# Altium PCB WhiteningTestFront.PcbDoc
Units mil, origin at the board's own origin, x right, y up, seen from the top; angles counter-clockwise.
Board outline 11100 x 1500 mil, 2 copper layers (Top Layer, Bottom Layer), stack 60.8 mil thick; 15 components, 48 nets, 141 pads, 16 vias.
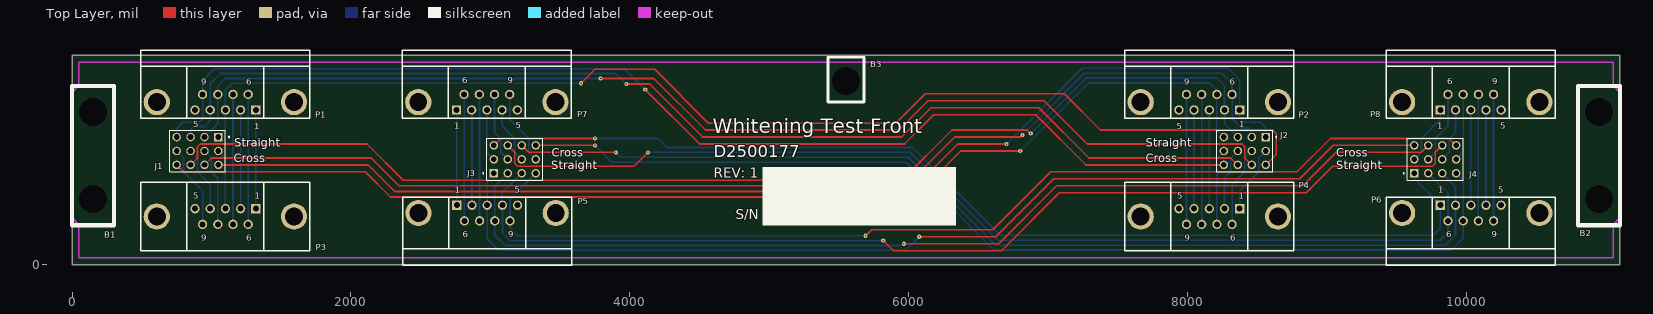
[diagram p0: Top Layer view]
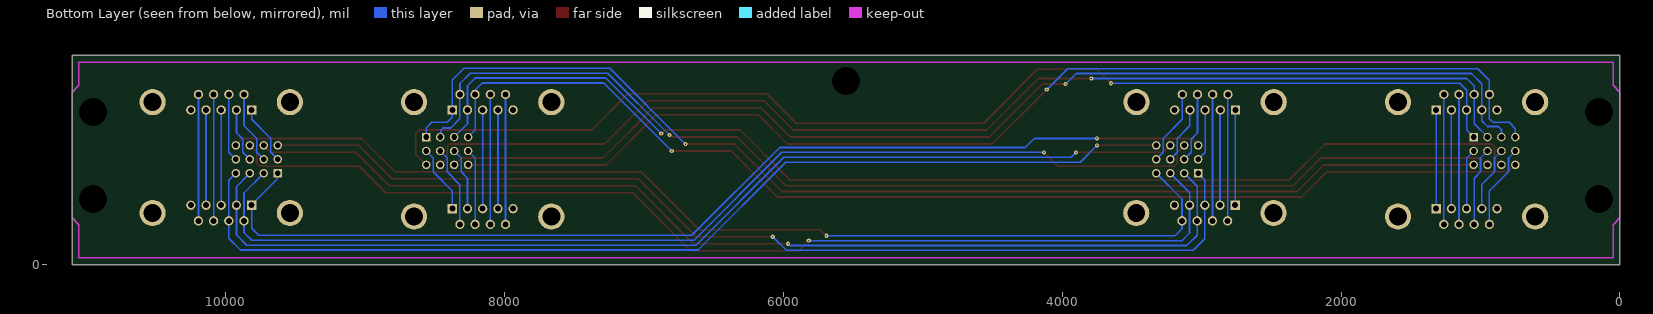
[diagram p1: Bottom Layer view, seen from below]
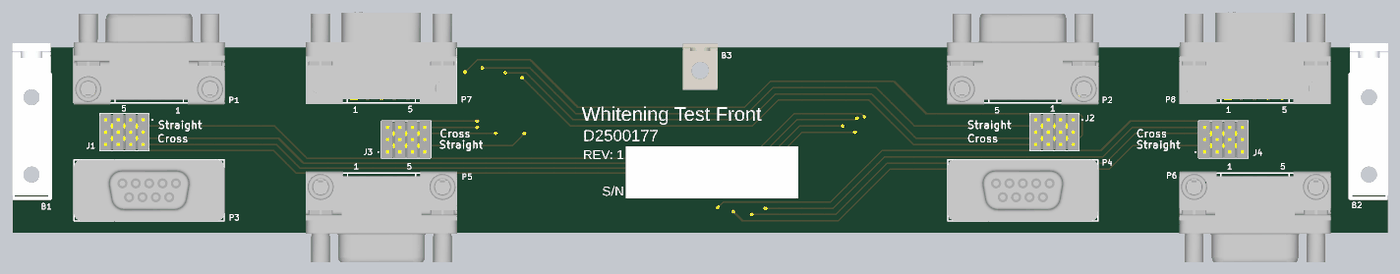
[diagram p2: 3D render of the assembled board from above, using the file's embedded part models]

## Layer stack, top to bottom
Top Solder: solder mask 0.4, Solder Resist, Dk 3.5
Top Layer: signal copper 1.4
Dielectric 1: dielectric 58, FR-4, Dk 4.8
Bottom Layer: signal copper 1.4
Bottom Solder: solder mask 0.4, Solder Resist, Dk 3.5

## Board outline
0,0 11100,0 11100,1500 0,1500

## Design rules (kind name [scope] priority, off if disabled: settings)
Clearance Clearance_relaydriver [HasFootprint('SOTFL50P160X60-6N')] p1: gap=10 ignorepadtopadclearanceinfootprint=TRUE except(8: Arc-Arc Arc-Track Arc-SMDPad Track-Track Track-SMDPad SMDPad-SMDPad)
Clearance Clearance_8mils [InNetClass('Clearance8mils') vs InNetClass('Clearance8mils')] p2: gap=10 ignorepadtopadclearanceinfootprint=TRUE except(8: Arc-Arc Arc-Track Track-Track)
Clearance [All] p3: gap=10 ignorepadtopadclearanceinfootprint=FALSE
ComponentClearance ComponentClearance_Collision [InComponentClass('ComponentCollision') vs InComponentClass('ComponentCollision')] p1: gap=-2000 collisioncheckmode=3 verticalgap=10 showdistances=FALSE
ComponentClearance [All] p2: gap=10 collisioncheckmode=3 verticalgap=10 showdistances=FALSE
HoleSize [All] p1: absolutevalues=TRUE maxlimit=200 minlimit=8 maxpercent=80.000 minpercent=20.000
MinimumAnnularRing [All] p1: minimumring=10
MinimumSolderMaskSliver [All] p1: minsoldermaskwidth=0
PolygonConnect [All] p1: connectstyle=Relief reliefconductorwidth=10 reliefentries=4 polygonreliefangle="90 Angle" airgapwidth=10
RoutingVias [All] p1: holewidth=15 width=35 viastyle="Through Hole" minholewidth=10 minwidth=25 maxholewidth=28 maxwidth=50
SilkToSolderMaskClearance [IsPad] p1: minsilkscreentomaskgap=2 clearancetoexposedcopper=TRUE
SolderMaskExpansion [All] p1: expansion=4 istentingtop=FALSE
Width [All] p1: maxlimit=100 minlimit=8 preferedwidth=10
26 further rules are at their usual default settings.

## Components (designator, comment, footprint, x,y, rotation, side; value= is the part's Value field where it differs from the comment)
B1 "Bracket" Bracket-RA_708#1 150,1095 r180 top
B2 "Bracket" Bracket-RA_708#2 10950,1095 r180 top
B3 "Bracket" Bracket-RA_634 5550,1317 r180 top
J1 "TSW-104-07-L-T" SAMTEC_TSW-104-07-L-T 900,815 r180 top
J2 "TSW-104-07-L-T" SAMTEC_TSW-104-07-L-T 8410,815 r180 top
J3 "TSW-104-07-L-T" SAMTEC_TSW-104-07-L-T 3175,755 r0 top
J4 "TSW-104-07-L-T" SAMTEC_TSW-104-07-L-T 9775,755 r0 top
P1 "DB9M" DB9M-RA 1100,1165 r0 top locked
P2 "DB9M" DB9M-RA 8155,1165 r0 top locked
P3 "DB9F" DB9F-ST 1100,345 r0 top locked
P4 "DB9F" DB9F-ST 8155,345 r0 top locked
P5 "DB9M" DB9M-RA 2977,370 r180 top locked
P6 "DB9M" DB9M-RA 10030,370 r180 top locked
P7 "DB9F" DB9F-RA 2975,1165 r0 top locked
P8 "DB9F" DB9F-RA 10030,1165 r0 top locked

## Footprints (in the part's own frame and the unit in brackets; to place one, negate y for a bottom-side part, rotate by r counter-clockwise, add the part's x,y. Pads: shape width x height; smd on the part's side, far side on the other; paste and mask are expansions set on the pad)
Bracket-RA_634 [mil] "Keystone Electronics right-angle 6-32 steel, 634"
  round 0 hole 200 unplated: 1(0,0)
  silkscreen extent -130,-170 130,150, body extent -141,-215 141,160, height 375
Bracket-RA_708#1 [mil] "Keystone Electronics right-angle 6-32 steel, 708"
  round 0 hole 200 unplated: 1(0,0) 2(0,625)
  silkscreen extent -150,-187 150,813, body extent -156,-439 156,791, height 390
Bracket-RA_708#2 [mil] "Keystone Electronics right-angle 6-32 steel, 708"
  round 0 hole 200 unplated: 1(0,0)
  oval 250x0 hole 200 unplated: 2(0,625)
  silkscreen extent -150,-187 150,813, body extent -156,-439 156,791, height 390
DB9F-RA [mm] "Receptiacle; D Subminiature 9 Position; Right Angle"
  rect 1.69x1.69 hole 1.09: 1(-5.54,-1.42)
  round 1.69 hole 1.09: 2(-2.77,-1.42) 3(0,-1.42) 4(2.77,-1.42) 5(5.54,-1.42) 6(-4.155,1.42) 7(-1.385,1.42) 8(1.385,1.42) 9(4.155,1.42)
  round 4.76 hole 3.26: 10(-12.495,0) 11(12.495,0)
  silkscreen extent -15.4,-2.9 15.4,9.5, body extent -15.49,-3.17 15.49,15.72, height 12.62
DB9F-ST [mm] "Receptiacle; D Subminiature 9 Position; Straight"
  rect 1.69x1.69 hole 1.09: 1(5.54,1.42)
  round 1.69 hole 1.09: 2(2.77,1.42) 3(0,1.42) 4(-2.77,1.42) 5(-5.54,1.42) 6(4.155,-1.42) 7(1.385,-1.42) 8(-1.385,-1.42) 9(-4.155,-1.42)
  round 4.76 hole 3.26: 10(12.495,0) 11(-12.495,0)
  silkscreen extent -15.4,-6.27 15.4,6.27, body extent -15.44,-6.3 15.44,6.3, height 12.32
DB9M-RA [mm] "Plug; D Subminiature 9 Position; Right Angle"
  rect 1.69x1.69 hole 1.09: 1(5.54,-1.42)
  round 1.69 hole 1.09: 2(2.77,-1.42) 3(0,-1.42) 4(-2.77,-1.42) 5(-5.54,-1.42) 6(4.155,1.42) 7(1.385,1.42) 8(-1.385,1.42) 9(-4.155,1.42)
  round 4.76 hole 3.26: 10(12.495,0) 11(-12.495,0)
  silkscreen extent -15.4,-2.9 15.4,9.5, body extent -15.52,-3.24 15.52,15.37, height 12.62
SAMTEC_TSW-104-07-L-T [mil]
  rect 61x61 hole 40.16: 01(-150,-100)
  round 61 hole 40.16: 02(-150,0) 03(-150,100) 04(-50,-100) 05(-50,0) 06(-50,100) 07(50,-100) 08(50,0) 09(50,100) 10(150,-100) 11(150,0) 12(150,100)
  silkscreen extent -230,-150 200,150, body extent -200,-150 200,150, height 330

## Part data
B1 B2: library part Bracket_708, "Keystone Electronics right-angle 6-32 steel, 708", Part Number=36-708-ND
B3: library part Bracket_634, "Keystone Electronics right-angle 6-32 steel, 634", Part Number=36-708-ND
J1 J2 J3 J4: Package=None
P1 P2 P5 P6: "Plug Assembly, 9 Position, Right Angle, .318 Series", Part Number=609-4954-ND
P3 P4: "Receptacle Assembly, 9 Position, Right Angle, .318 Series", Part Number=609-5874-ND
P7 P8: "Receptacle Assembly, 9 Position, Right Angle, .318 Series", Part Number=609-6160-ND

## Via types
v1: diameter 30, hole 10, Top Layer to Bottom Layer, 16 vias

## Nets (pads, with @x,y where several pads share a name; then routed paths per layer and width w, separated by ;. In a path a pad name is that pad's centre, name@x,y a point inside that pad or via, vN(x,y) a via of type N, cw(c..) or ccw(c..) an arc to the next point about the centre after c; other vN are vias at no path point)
IN0: P1.6 P3.6 | length 931.8
  Bottom Layer w12: P3.6 P1.6
IN1: P1.7 P3.7 | length 931.8
  Bottom Layer w12: P3.7 P1.7
IN2: J1.05 P3.8 | length 565.5
  Bottom Layer w12: J1.05 1000,765 1000,665 1045.47,619.53 P3.8
IN3: J1.11 P3.9 | length 603.1
  Bottom Layer w12: J1.11 800,765 800,665 936.42,528.58 P3.9
IN4: J2.05 P4.6 | length 584.5
  Bottom Layer w12: P4.6 8318.58,573.58 8410,665 8410,765 J2.05
IN5: J2.11 P4.7 | length 546.8
  Bottom Layer w12: P4.7 8209.53,764.53 J2.11
IN6: P2.8 P4.8 | length 931.8
  Bottom Layer w12: P4.8 P2.8
IN7: P2.9 P4.9 | length 931.8
  Bottom Layer w12: P4.9 P2.9
INN2: J1.04 J2.06 P1.8 | length 8319.8
  Top Layer w12: v1(3790,1335) 4172.35,1335 4542.35,965 5928.58,965 6138.58,1175 6970,1175 7280,865 8390,865 8410,845 8410,765 J2.06
  Bottom Layer w12: J1.04 1045.47,1010.47 P1.8 1045.47,1280.47 1100,1335 v1(3790,1335)
INN3: J1.10 J2.12 P1.9 | length 8369
  Top Layer w12: v1(4110.93,1255) 4500.93,865 ; 4500.93,865 5970,865 6180,1075 6911.45,1075 7271.45,715 J2.12
  Bottom Layer w12: J1.10 750,975 795,1020 910,1020 936.42,1046.42 P1.9 936.42,1321.42 1020,1405 3960.93,1405 v1(4110.93,1255)
INN4: J1.06 J2.04 P2.6 | length 8311.6
  Top Layer w12: J1.06 1000,765 2145,765 2345,565 5980.71,565 6330.71,915 6801,915 v1(6815.5,929.5)
  Bottom Layer w12: v1(6815.5,929.5) 7258.81,1372.81 8244.2,1372.81 8318.25,1298.75 P2.6@8318.25,1220.91 ; P2.6 8318.58,1046.42 8385,980 8440,980 8456.5,963.5 8456.5,918.5 J2.04
INN5: J1.12 J2.10 P2.7 | length 8272.6
  Top Layer w12: J1.12 800,665 2103.58,665 2283.58,485 6042.13,485 6372.13,815 v1(6800,815)
  Bottom Layer w12: v1(6800,815) 7287.81,1302.81 8159.2,1302.81 8209.2,1252.81 P2.7@8209.2,1220.91 ; P2.7 8209.53,965.47 J2.10
INP0: P1.1 P3.1 | length 708.2
  Bottom Layer w12: P3.1 P1.1
INP1: P1.2 P3.2 | length 708.2
  Bottom Layer w12: P3.2 P1.2
INP2: J1.01 J2.03 P1.3 | length 8573.4
  Top Layer w12: v1(3650,1300) 3750,1400 4178.06,1400 4563.06,1015 5907.87,1015 6117.87,1225 7115,1225 7375,965 8610,965 8635,940 8635,790 J2.03
  Bottom Layer w12: J1.01 1100,965 P1.3 1100,1250 1150,1300 v1(3650,1300)
INP3: J1.07 J2.09 P1.4 | length 8330.1
  Top Layer w12: v1(3975,1295) 4141.64,1295 4521.64,915 5949.29,915 6159.29,1125 6932.16,1125 7292.16,765 8310,765 J2.09
  Bottom Layer w12: J1.07 850,968.15 871.85,990 950,990 990.94,1030.94 P1.4 990.94,1295.94 1065,1370 3900,1370 v1(3975,1295)
INP4: J1.03 J2.01 P2.1 | length 8353.2
  Top Layer w12: J1.03 2124.29,715 2314.29,525 6011.42,525 6351.42,865 v1@6700.75,865
  Bottom Layer w12: v1(6700.75,864.25) 7244.31,1407.81 8289.2,1407.81 8372.78,1324.22 P2.1@8372.78,1109.09 ; P2.1 8373.11,1056.89 8410,1020 8520,1020 8560,980 J2.01
INP5: J1.09 J2.07 P2.2 | length 8385.5
  Top Layer w12: J1.09 900,765 900,845 920,865 2115,865 2375,605 5950,605 6310,965 6850,965 v1(6875.25,939.75)
  Bottom Layer w12: v1(6875.25,939.75) 7273.31,1337.81 8209.2,1337.81 8263.72,1283.28 P2.2@8263.72,1109.09 ; P2.2 8264.06,1010.94 J2.07
INP6: P2.3 P4.3 | length 708.2
  Bottom Layer w12: P4.3 P2.3
INP7: P2.4 P4.4 | length 708.2
  Bottom Layer w12: P4.4 P2.4
IP2: J1.02 P3.3 | length 434.8
  Bottom Layer w12: J1.02 1100,765 P3.3
IP3: J1.08 P3.4 | length 472.5
  Bottom Layer w12: J1.08 900,765 900,665 990.95,574.05 P3.4
IP4: J2.02 P4.1 | length 491.5
  Bottom Layer w12: P4.1 8373.11,528.11 8510,665 8510,765 J2.02
IP5: J2.08 P4.2 | length 453.8
  Bottom Layer w12: P4.2 8264.06,619.06 8310,665 8310,765 J2.08
ON0: P5.6 P7.6 | length 901.8
  Bottom Layer w12: P5.6@2813.42,319.09 P7.6@2813.42,1220.91
ON1: P5.7 P7.7 | length 901.8
  Bottom Layer w12: P5.7@2922.47,319.09 P7.7@2922.47,1220.91
ON2: J3.04 J4.06 P5.8 | length 7503.6
  Top Layer w12: v1(5965,150) 6644.29,150 7059.29,565 8825,565 9065,805 9675,805 J4.06
  Bottom Layer w12: P5.8@3031.53,289.09 3031.53,561.53 J3.04 ; P5.8@3031.86,289.09 3031.86,211.25 3105.91,137.19 5952.19,137.19 v1(5965,150)
ON3: J3.10 J4.12 P5.9 | length 7588.7
  Top Layer w12: v1(5690.91,207.19) 5733.72,250 6602.87,250 7017.87,665 8783.58,665 9023.58,905 9875,905 J4.12
  Bottom Layer w12: P5.9@3140.58,289.09 3140.58,470.58 J3.10 ; P5.9@3140.91,289.09 3140.91,257.19 3190.91,207.19 v1(5690.91,207.19)
ON4: J3.06 J4.04 P6.6 | length 7659.4
  Top Layer w12: J3.06 3175,805 3175,725 3195,705 4030,705 v1(4130,805)
  Bottom Layer w12: v1(4130,805) 6010.5,805 6640.5,175 9811.89,175 9866.42,229.53 9866.42,289.09 9866.42,513.58 J4.04
ON5: J3.12 J4.10 P6.7 | length 7483.1
  Top Layer w12: J3.12 v1(3750,855)
  Bottom Layer w12: v1(3750,855) 3870,735 5981.51,735 6611.51,105 9891.89,105 9975.47,188.58 9975.47,289.09 9975.47,604.53 J4.10
ON6: P6.8 P8.8 | length 901.8
  Bottom Layer w12: P6.8@10084.53,319.09 P8.8
ON7: P6.9 P8.9 | length 901.8
  Bottom Layer w12: P6.9@10193.58,319.09 P8.9
OP0: P5.1 P7.1 | length 678.2
  Bottom Layer w12: P5.1@2758.89,430.9 P7.1@2758.89,1109.09
OP1: P5.2 P7.2 | length 678.2
  Bottom Layer w12: P5.2@2867.94,430.9 P7.2@2867.94,1109.09
OP2: J3.01 J4.03 P5.3 | length 7483.2
  Top Layer w12: v1(6075,200) 6623.58,200 7038.58,615 8804.29,615 9044.29,855 J4.03
  Bottom Layer w12: P5.3@2977,400.9 2977,607 J3.01 ; P5.3@2977.33,400.9 2977.33,185.78 3060.91,102.19 5977.19,102.19 v1(6075,200)
OP3: J3.07 J4.09 P5.4 | length 7636.7
  Top Layer w12: v1(5817.5,172.5) 5890,100 6665,100 7080,515 8850,515 9040,705 9755,705 9775,725 9775,805 J4.09
  Bottom Layer w12: P5.4@3086.06,400.9 3086.06,516.06 J3.07 ; P5.4@3086.39,400.9 3086.39,226.72 3140.91,172.19 v1@5817.5,172.19
OP4: J3.03 J4.01 P6.1 | length 7558.6
  Top Layer w12: J3.03 3075,905 v1(3750,905)
  Bottom Layer w12: v1(3750,905) 4200,905 4265,840 6025,840 6655,210 9761.89,210 9811.89,260 P6.1@9811.89,400.9 ; J4.01 9629.27,650.73 9629.27,613.53 P6.1@9811.89,430.9
OP5: J3.09 J4.07 P6.2 | length 7503.5
  Top Layer w12: J3.09 3275,805 v1(3900,805)
  Bottom Layer w12: v1(3900,805) 3935,770 5996,770 6626.01,140 9846.89,140 9920.94,214.06 9920.94,400.9 9920.94,559.06 J4.07
OP6: P6.3 P8.3 | length 678.2
  Bottom Layer w12: P6.3@10030,430.9 P8.3
OP7: P6.4 P8.4 | length 678.2
  Bottom Layer w12: P6.4@10139.06,430.9 P8.4
OUTN2: J3.05 P7.8 | length 505.5
  Bottom Layer w12: P7.8 3029.53,945.47 3075,900 3075,805 J3.05
OUTN3: J3.11 P7.9 | length 543.1
  Bottom Layer w12: P7.9 3138.58,1041.42 3275,905 3275,805 J3.11
OUTN4: J4.05 P8.6 | length 524.5
  Bottom Layer w12: J4.05 9775,805 9775,905 9866.42,996.42 P8.6
OUTN5: J4.11 P8.7 | length 486.8
  Bottom Layer w12: J4.11 9975.47,805.47 P8.7
OUTP2: J3.02 P7.3 | length 374.8
  Bottom Layer w12: P7.3 2975,805 J3.02
OUTP3: J3.08 P7.4 | length 412.5
  Bottom Layer w12: P7.4 3084.06,995.94 3175,905 3175,805 J3.08
OUTP4: J4.02 P8.1 | length 431.5
  Bottom Layer w12: J4.02 9675,805 9675,905 9811.89,1041.89 P8.1
OUTP5: J4.08 P8.2 | length 393.8
  Bottom Layer w12: J4.08 9875,805 9875,900 9920.94,945.94 P8.2
pads on no net: B1.1 B1.2 B2.1 B2.2 B3.1 P1.5 P1.10 P1.11 P2.5 P2.10 P2.11 P3.5 P3.10 P3.11 P4.5 P4.10 P4.11 P5.5 P5.10 P5.11 P6.5 P6.10 P6.11 P7.5 P7.10 P7.11 P8.5 P8.10 P8.11

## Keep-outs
Keep-Out Layer:
  lines w10: 0,335 0,1235 50,1285 50,1450 11050,1450 11050,1285 11100,1235 11100,335 11050,285 11050,50 50,50 50,285 0,335

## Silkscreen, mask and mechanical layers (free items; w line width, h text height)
Top Overlay:
  region: 6340,280 6340,700 4950,700 4950,280
  text "Whitening Test Front" at 4593,907 h180
  text "Straight" at 1165,845.01 h60
  text "Straight" at 7700,845.01 h60
  text "Cross" at 3440,775.01 h60
  text "Cross" at 9065,775.01 h60
  text "D2500177" at 4603,742 h150
  text "Cross" at 1160,735.01 h60
  text "Cross" at 7700,735.01 h60
  text "Straight" at 3435,685.01 h60
  text "Straight" at 9065,685.01 h60
  text "REV: 1" at 4603,597 h120
  text "S/N" at 4758,302 h120
Mechanical 1:
  the board outline again, w10
Drill Drawing:
  circle w10: c100.62,2235.83 r33.33
  lines w10: 67.29,2369.17 83.96,2369.17 100.62,2352.5 117.29,2369.17 133.96,2369.17 117.29,2385.83 133.96,2402.5 117.29,2402.5 100.62,2419.17 83.96,2402.5 67.29,2402.5 83.96,2385.83 67.29,2369.17 ; 67.29,2502.5 133.96,2502.5 133.96,2569.17 67.29,2569.17 67.29,2502.5 ; 67.29,2719.17 133.96,2719.17 100.62,2652.5 67.29,2719.17 ; 67.29,2802.5 100.62,2819.17 133.96,2802.5 117.29,2835.83 133.96,2869.17 100.62,2852.5 67.29,2869.17 83.96,2835.83 67.29,2802.5
  lines w15: 7.5,2157.5 10598.56,2157.5 ; 7.5,2907.5 10598.56,2907.5 ; 558.38,2007.5 558.38,3057.5 ; 1148.22,2007.5 1148.22,3057.5 ; 2307.88,2007.5 2307.88,3057.5 ; 2813.76,2007.5 2813.76,3057.5 ; 3547.56,2007.5 3547.56,3057.5 ; 5047.11,2007.5 5047.11,3057.5 ; 5636.96,2007.5 5636.96,3057.5 ; 6382.76,2007.5 6382.76,3057.5 ; 7032.58,2007.5 7032.58,3057.5 ; 7886.35,2007.5 7886.35,3057.5 ; 9219.96,2007.5 9219.96,3057.5 ; 7.5,2007.5 10598.56,2007.5 10598.56,3057.5 7.5,3057.5 7.5,2007.5
  text "Symbol" at 97.5,2952.5 h72
  text "Count" at 603.38,2952.5 h72
  text "Hole Size" at 1193.22,2952.5 h72
  text "Plated" at 2352.88,2952.5 h72
  text "Hole Type" at 2858.76,2952.5 h72
  text "Drill Layer Pair" at 3592.56,2952.5 h72
  text "Via/Pad" at 5092.11,2952.5 h72
  text "Pad Shape" at 5681.96,2952.5 h72
  text "Template" at 6427.76,2952.5 h72
  text "Description" at 7077.58,2952.5 h72
  text "Hole Tolerance (+)" at 7931.35,2952.5 h72
  text "Hole Tolerance (-)" at 9264.96,2952.5 h72
  text "5" at 603.38,2802.5 h60
  text "200.00mil (5.080mm)" at 1193.22,2802.5 h60
  text "NPTH" at 2352.88,2802.5 h60
  text "Round" at 2858.76,2802.5 h60
  text "Top Layer - Bottom Layer" at 3592.56,2802.5 h60
  text "Pad" at 5092.11,2802.5 h60
  text "Rounded" at 5681.96,2802.5 h60
  text "(Mixed)" at 6427.76,2802.5 h60
  text "16" at 603.38,2652.5 h60
  text "10.00mil (0.254mm)" at 1193.22,2652.5 h60
  text "PTH" at 2352.88,2652.5 h60
  text "Round" at 2858.76,2652.5 h60
  text "Top Layer - Bottom Layer" at 3592.56,2652.5 h60
  text "Via" at 5092.11,2652.5 h60
  text "Rounded" at 5681.96,2652.5 h60
  text "v76h25" at 6427.76,2652.5 h60
  text "16" at 603.38,2502.5 h60
  text "128.35mil (3.260mm)" at 1193.22,2502.5 h60
  text "PTH" at 2352.88,2502.5 h60
  text "Round" at 2858.76,2502.5 h60
  text "Top Layer - Bottom Layer" at 3592.56,2502.5 h60
  text "Pad" at 5092.11,2502.5 h60
  text "Rounded" at 5681.96,2502.5 h60
  text "c476h326" at 6427.76,2502.5 h60
  text "48" at 603.38,2352.5 h60
  text "40.16mil (1.020mm)" at 1193.22,2352.5 h60
  text "PTH" at 2352.88,2352.5 h60
  text "Round" at 2858.76,2352.5 h60
  text "Top Layer - Bottom Layer" at 3592.56,2352.5 h60
  text "Pad" at 5092.11,2352.5 h60
  text "(Mixed)" at 5681.96,2352.5 h60
  text "(Mixed)" at 6427.76,2352.5 h60
  text "72" at 603.38,2202.5 h60
  text "42.91mil (1.090mm)" at 1193.22,2202.5 h60
  text "PTH" at 2352.88,2202.5 h60
  text "Round" at 2858.76,2202.5 h60
  text "Top Layer - Bottom Layer" at 3592.56,2202.5 h60
  text "Pad" at 5092.11,2202.5 h60
  text "(Mixed)" at 5681.96,2202.5 h60
  text "(Mixed)" at 6427.76,2202.5 h60
  text "157 Total" at 603.38,2052.5 h60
